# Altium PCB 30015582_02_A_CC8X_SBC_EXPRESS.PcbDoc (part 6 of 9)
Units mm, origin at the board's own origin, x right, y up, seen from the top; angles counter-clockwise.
Board outline 87 x 63 mm, 6 copper layers (Top Layer-L1, GND Plane-L2, Signal-L3, PWR/Signal-L4, GND Plane-L5, Bottom Layer-L6), stack 1.172 mm thick; 169 components, 171 nets, 693 pads, 391 vias.
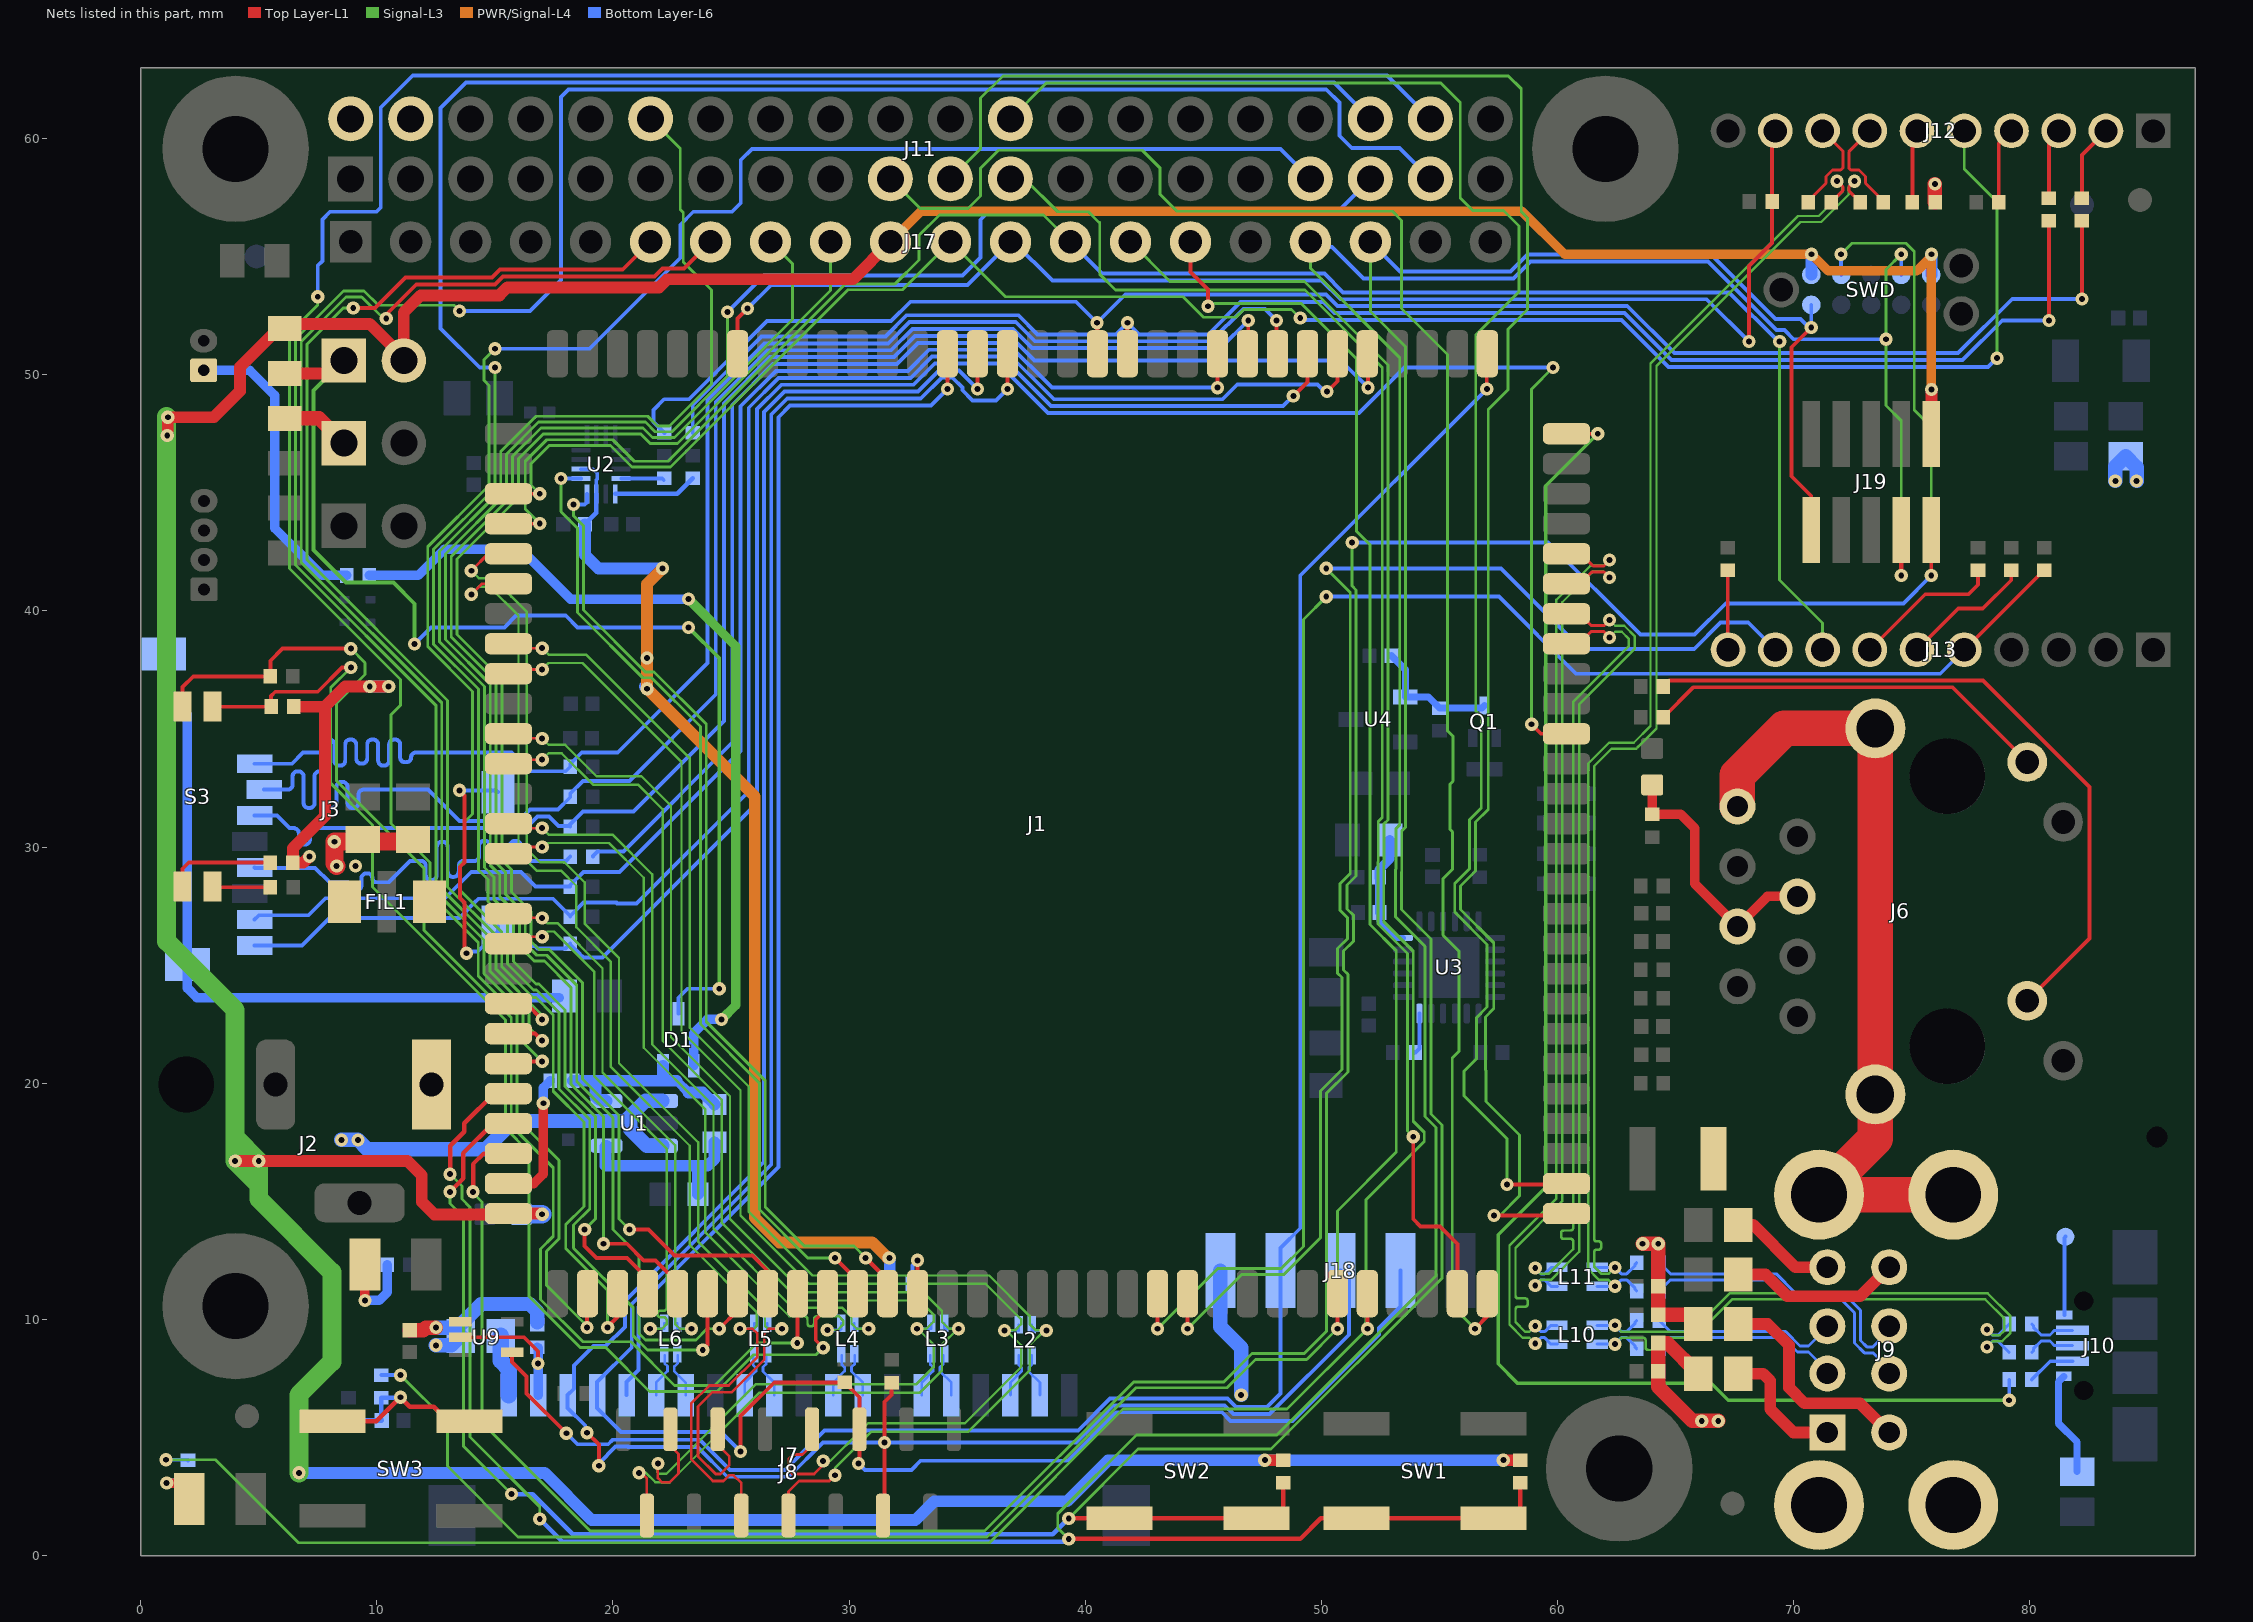
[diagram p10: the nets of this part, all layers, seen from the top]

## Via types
v1: diameter 0.56, hole 0.25, Top Layer-L1 to Bottom Layer-L6, 391 vias

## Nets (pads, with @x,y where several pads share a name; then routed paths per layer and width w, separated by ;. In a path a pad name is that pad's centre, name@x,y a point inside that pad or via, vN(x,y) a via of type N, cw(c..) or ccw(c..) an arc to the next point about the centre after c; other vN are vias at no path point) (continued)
MCA_IO1: J1.52 J17.6 | length 50.8
  Top Layer-L1 w0.165: v1(9,52.825) 9.925,52.825 11.21,54.11 14.877,54.11 15.217,54.45 20.414,54.45 J17.6@21.59,55.626 ; J1.52@15.573,23.368 16.332,23.368 v1(17,22.7)
  Signal-L3 w0.122: v1(9,52.825) 8.576,52.825 7.05,51.299 7.05,42.154 12.996,36.208 12.996,28.312 15.039,26.27 15.039,24.844 17,22.882 v1(17,22.7)
MCA_IO2: J1.53 J17.7 | length 55.3
  Top Layer-L1 w0.165: v1(10.4,52.375) 10.4,52.55 11.668,53.818 14.998,53.818 15.338,54.158 21.759,54.158 22.102,54.501 23.005,54.501 J17.7@24.13,55.626 ; J1.53@15.573,22.098 16.702,22.098 v1(17,21.8)
  Signal-L3 w0.122: v1(10.4,52.375) 10.277,52.375 9.359,53.293 8.692,53.293 6.801,51.402 6.801,42.051 12.747,36.105 12.747,28.209 14.79,26.166 14.79,24.741 16.438,23.092 16.438,22.362 v1(17,21.8)
MCA_IO3: J1.54 J11.37 | length 96.4
  Top Layer-L1 w0.165: J1.54@15.573,20.828 15.67,20.925 v1(17,20.925)
  Signal-L3 w0.122: v1(13.5,52.7) 13.262,52.938 10.065,52.938 9.462,53.542 8.589,53.542 6.552,51.505 6.552,41.948 12.498,36.002 12.498,28.106 14.541,26.063 14.541,24.637 16.189,22.989 16.189,21.736 v1(17,20.925)
  Bottom Layer-L6 w0.165: v1(13.5,52.7) 16.485,52.7 17.795,54.01 17.795,61.755 18.121,62.081 50.204,62.081 50.763,61.522 50.763,60.117 51.28,59.6 53.303,59.6 J11.37@54.61,58.293
MCA_IO4: J1.61 J11.38 | length 107.6
  Top Layer-L1 w0.165: v1(18.9,9.65) 18.9,11.065 J1.61@18.923,11.088
  Signal-L3 w0.121: 6.3,49.5 6.3,51.755 7.5,52.955 v1(7.5,53.3)
  Signal-L3 w0.122: 6.3,49.5 6.3,41.8 11,37.1 11,36 10.6,35.6 10.6,31 12.249,29.351 12.249,28.003 14.292,25.96 14.292,24.534 15.94,22.886 15.94,18.51 17.717,16.733 17.717,13.415 17.182,12.88 17.182,11.441 18.9,9.723 v1(18.9,9.65)
  Bottom Layer-L6 w0.165: v1(7.5,53.3) 7.5,54.621 7.692,54.813 7.692,56.577 8.014,56.9 9.985,56.9 10.165,57.08 10.165,61.311 11.519,62.665 52.778,62.665 J11.38@54.61,60.833
MCA_IO5: J1.62 J11.33 | length 89.2
  Top Layer-L1 w0.165: v1(19.775,9.65) 19.775,9.675 20.193,10.093 J1.62@20.193,11.088
  Signal-L3 w0.121: 14.751,48.5 14.751,49.549 14.533,49.767 14.533,50.632 v1(15,51.1)
  Signal-L3 w0.122: 14.751,48.5 14.751,45.311 12.155,42.716 12.155,38.484 14.055,36.584 14.055,31.4 13.71,31.055 13.71,29.45 13.5,29.24 13.5,28.187 15.287,26.4 15.287,24.947 16.612,23.622 16.74,23.622 17.468,22.894 17.468,19.657 18.768,18.357 18.768,14.782 18,14.014 18,12.993 19.775,11.218 v1(19.775,9.65)
  Bottom Layer-L6 w0.165: v1(15,51.1) 19,51.1 22.85,54.95 22.85,56.35 23.4,56.9 25.035,56.9 25.41,57.275 25.41,59.085 25.885,59.56 48.263,59.56 J11.33@49.53,58.293
MCA_IO6: J1.63 J11.12 | length 64.3
  Top Layer-L1 w0.165: v1(18.8,13.8) 18.8,13.1 19.3,12.6 20.6,12.6 21.463,11.737 J1.63@21.463,11.088
  Signal-L3 w0.121: 15.249,46.6 15.249,46.749 16.743,48.243 21.473,48.243 21.883,47.833 22.394,47.833 24.165,49.604 24.165,53.588 22.974,54.779 22.974,56.865 22.85,56.989 22.85,59.573 J11.12@21.59,60.833
  Signal-L3 w0.122: 15.249,46.6 15.249,45.105 12.653,42.509 12.653,38.691 14.553,36.791 14.553,29.128 14.953,28.728 14.953,27.791 15.785,26.959 15.785,25.153 16.738,24.2 16.866,24.2 17.966,23.1 17.966,19.863 19.266,18.563 19.266,14.266 v1(18.8,13.8)
MCA_IO7: J1.64 J11.35 | length 86.1
  Top Layer-L1 w0.165: v1(19.6,13.2) 20.6,13.2 21.3,12.5 21.8,12.5 22.733,11.567 J1.64@22.733,11.088
  Signal-L3 w0.121: 21.271,47.994 21.371,47.994 21.781,47.584 22.496,47.584 24.85,49.938 v1(24.85,52.65)
  Signal-L3 w0.122: v1(19.6,13.2) 19.6,18.581 18.215,19.966 18.215,24.047 17.094,25.168 16.666,25.168 16.034,25.8 16.034,27.062 15.202,27.894 15.202,28.831 14.802,29.231 14.802,36.894 12.902,38.794 12.902,42.406 15.498,45.002 15.498,46.646 16.846,47.994 21.271,47.994
  Bottom Layer-L6 w0.165: v1(24.85,52.65) 26.4,54.2 34.8,54.2 35.555,54.955 35.555,56.563 35.932,56.94 50.717,56.94 J11.35@52.07,58.293
MCA_IO8: J1.65 J11.36 | length 104.7
  Top Layer-L1 w0.165: v1(23.8,8.7) 24.003,8.903 J1.65@24.003,11.088
  Signal-L3 w0.122: v1(15,50.3) 15,45.208 12.404,42.612 12.404,38.588 14.304,36.688 14.304,29.025 14.704,28.625 14.704,27.688 15.536,26.856 15.536,25.05 16.635,23.951 16.763,23.951 17.717,22.997 17.717,19.76 19.017,18.46 19.017,14.679 18.332,13.994 18.332,13.013 20.858,10.487 20.858,9.303 21.461,8.7 v1(23.8,8.7)
  Bottom Layer-L6 w0.165: v1(15,50.3) 14.358,50.3 12.695,51.963 12.695,61.301 13.767,62.373 50.53,62.373 J11.36@52.07,60.833
MCA_IO9: J1.66 J17.8 | length 65.5
  Top Layer-L1 w0.165: v1(24.5,9.6) 25.273,10.373 J1.66@25.273,11.088
  Signal-L3 w0.122: v1(24.5,9.6) 23.987,9.6 23.519,9.132 21.381,9.132 21.107,9.406 21.107,12.693 20,13.8 20,18.533 18.464,20.069 18.464,24.15 17.197,25.417 16.769,25.417 16.283,25.903 16.283,27.165 15.451,27.997 15.451,28.934 15.051,29.334 15.051,36.997 13.151,38.897 13.151,42.303 15.747,44.899 15.747,46.543 16.949,47.745 21.268,47.745 21.678,47.336 22.599,47.336 27.6,52.337 27.6,54.696 J17.8@26.67,55.626
MCA_IO10: J1.67 J17.9 | length 63.1
  Top Layer-L1 w0.165: v1(20.7,13.8) 21.5,13.8 22.6,12.7 25.9,12.7 26.543,12.057 J1.67@26.543,11.088
  Signal-L3 w0.122: v1(20.7,13.8) 20.249,14.251 20.249,18.636 18.713,20.173 18.713,24.253 17.3,25.666 16.872,25.666 16.532,26.006 16.532,27.268 15.7,28.1 15.7,29.038 15.3,29.438 15.3,37.1 13.4,39 13.4,42.2 15.996,44.796 15.996,46.44 17.052,47.496 21.165,47.496 21.575,47.087 22.731,47.087 29.21,53.566 J17.9@29.21,55.626
MCA_VIN_DET: J1.58 R9.1 | length 5.7
  Top Layer-L1 w0.4: J1.58@15.573,15.748 16.648,15.748 17.05,16.15 v1(17.05,19.15)
  Bottom Layer-L6 w0.4: v1(17.05,19.15) 17.05,19.805 R9.1@17.345,20.1
MIPI_DSI0_CLK_N: J1.37 J8.11 L5.1 | length 52.8
  Top Layer-L1 w0.114: v1(14,41.7) 14.718,42.418 J1.37@15.573,42.418 ; J8.11@24.433,5.344 24.433,4.692 24.925,4.2 24.925,3.825 24.55,3.45 24.35,3.45 23.6,4.2 23.6,6.308 24.2,6.908 25.021,6.908 26.406,8.293 26.406,9.4 26.606,9.6 v1(27.15,9.6)
  Signal-L3 w0.102: v1(14,41.7) 14.322,41.378 14.925,41.378 15.7,40.603 16.356,39.947 16.356,29.907 16.907,29.356 17.947,29.356 18.797,28.506 18.797,26.755 20.256,25.297 20.256,20.847 23.606,17.497 23.606,13.294 26.438,10.462 26.438,9.719 26.557,9.6 v1(27.15,9.6)
  Bottom Layer-L6 w0.114: L5.1@26.534,9.837 26.534,9.6 v1(27.15,9.6)
MIPI_DSI0_CLK_P: J1.38 J8.10 L5.4 | length 52.8
  Top Layer-L1 w0.114: v1(14,40.7) 14.448,41.148 J1.38@15.573,41.148 ; v1(25.375,9.6) 25.914,9.6 26.114,9.4 26.114,8.414 24.9,7.2 24.079,7.2 23.308,6.429 23.308,4.079 24.229,3.158 24.671,3.158 24.907,3.393 25.107,3.393 25.433,3.067 J8.10@25.433,1.694
  Signal-L3 w0.102: v1(14,40.7) 14.322,41.022 14.778,41.022 16,39.8 16,29.76 16.76,29 17.8,29 18.442,28.358 18.442,26.608 19.9,25.15 19.9,20.7 23.25,17.35 23.25,13.147 26.082,10.315 26.082,9.719 25.963,9.6 v1(25.375,9.6)
  Bottom Layer-L6 w0.114: v1(25.375,9.6) 25.984,9.6 L5.4@25.984,9.837
MIPI_DSI0_DATA0_N: J1.40 J8.8 L2.1 | length 61.1
  Top Layer-L1 w0.114: J1.40@15.573,38.608 15.761,38.42 v1(17,38.42) ; J8.8@27.433,1.694 27.433,2.708 27.883,3.158 29.158,3.158 v1(29.4,3.4)
  Signal-L3 w0.102: v1(17,38.42) 17.272,38.148 18.855,38.148 23.256,33.747 23.256,22.347 25.756,19.847 25.756,14.544 28.444,11.856 35.931,11.856 37.639,10.147 37.639,9.8 37.907,9.532 v1@38.271,9.532 ; v1(29.4,3.4) 29.4,3.7 30.947,5.247 35.047,5.247 37.639,7.839 37.639,8.9 v1@38.271,9.532 ; v1(38.35,9.525) 38.278,9.525 v1@38.271,9.532
  Bottom Layer-L6 w0.114: L2.1@37.736,9.769 37.736,9.532 37.743,9.525 v1(38.35,9.525)
MIPI_DSI0_DATA0_P: J1.41 J8.7 L2.4 | length 61.1
  Top Layer-L1 w0.114: J1.41@15.573,37.338 15.755,37.52 v1(17,37.52) ; J8.7@28.433,5.344 28.433,4.683 28.025,4.275 27.625,4.275 27.45,4.1 27.45,3.593 27.593,3.45 28.517,3.45 28.9,3.833 v1(28.9,4)
  Signal-L3 w0.102: v1(17,37.52) 17.272,37.792 18.708,37.792 22.9,33.6 22.9,22.2 25.4,19.7 25.4,14.397 28.297,11.5 35.784,11.5 37.284,10 37.284,9.8 37.016,9.532 v1@36.652,9.532 ; v1(28.9,4) 29.197,4 30.497,5.3 30.8,5.603 34.9,5.603 37.284,7.986 37.284,8.9 v1@36.652,9.532 ; v1(36.575,9.525) 36.645,9.525 v1@36.652,9.532
  Bottom Layer-L6 w0.114: v1(36.575,9.525) 37.179,9.525 37.186,9.532 L2.4@37.186,9.769
MIPI_DSI0_DATA1_N: J1.43 J8.14 L3.1 | length 58.4
  Top Layer-L1 w0.114: J1.43@15.573,34.798 15.771,34.6 v1(17,34.6) ; v1(21.1,3.5) 21.2,3.5 21.433,3.267 J8.14@21.433,1.694
  Signal-L3 w0.102: v1(17,34.6) 17.272,34.328 17.972,34.328 19.3,33 21.2,33 22.456,31.744 22.456,21.947 24.956,19.447 24.956,14.244 28.044,11.156 33.122,11.156 33.931,10.347 33.931,9.9 34.231,9.6 v1@34.603,9.6 ; v1(21.1,3.5) 21.397,3.5 21.797,3.1 22.4,3.1 26.2,6.9 33,6.9 33.931,7.831 33.931,8.928 v1@34.603,9.6 ; v1(34.626,9.6) v1@34.603,9.6
  Bottom Layer-L6 w0.114: L3.1@34.027,9.837 34.027,9.6 v1(34.626,9.6)
MIPI_DSI0_DATA1_P: J1.44 J8.13 L3.4 | length 58.4
  Top Layer-L1 w0.114: J1.44@15.573,33.528 15.745,33.7 v1(17,33.7) ; v1(21.9,3.9) 21.9,3.275 22.075,3.1 22.4,3.1 22.775,3.475 22.775,4.3 22.433,4.642 J8.13@22.433,5.344
  Signal-L3 w0.102: v1(17,33.7) 17.272,33.972 17.825,33.972 19.153,32.644 21.053,32.644 22.1,31.597 22.1,21.8 24.6,19.3 24.6,14.097 27.897,10.8 32.975,10.8 33.575,10.2 33.575,9.9 33.275,9.6 v1@32.903,9.6 ; v1(21.9,3.9) 21.9,3.5 21.944,3.456 22.253,3.456 26.053,7.256 32.853,7.256 33.575,7.978 33.575,8.928 v1@32.903,9.6 ; v1(32.875,9.6) v1@32.903,9.6
  Bottom Layer-L6 w0.114: v1(32.875,9.6) 33.477,9.6 L3.4@33.477,9.837
MIPI_DSI0_DATA2_N: J1.46 L4.1 | length 32.4
  Top Layer-L1 w0.114: J1.46@15.573,30.988 15.761,30.8 v1(17,30.8)
  Signal-L3 w0.102: v1(17,30.8) 17.272,30.528 19.975,30.528 21.656,28.847 21.656,21.647 24.256,19.047 24.256,13.844 27.613,10.487 29.713,10.487 30.1,10.1 30.1,9.821 30.321,9.6 v1(30.825,9.6)
  Bottom Layer-L6 w0.114: L4.1@30.217,9.837 30.217,9.6 v1(30.825,9.6)
MIPI_DSI0_DATA2_P: J1.47 L4.4 | length 32.4
  Top Layer-L1 w0.114: J1.47@15.573,29.718 15.855,30 v1(17,30)
  Signal-L3 w0.102: v1(17,30) 17.1,30 17.272,30.172 19.828,30.172 21.3,28.7 21.3,21.5 23.9,18.9 23.9,13.697 27.466,10.132 27.975,10.132 28.111,10.132 cw(c28.111,10.007) 28.235,10.007 28.235,9.825 ccw(c28.36,9.825) 28.36,9.7 28.387,9.7 ccw(c28.387,9.825) 28.512,9.825 28.512,10.007 cw(c28.636,10.007) 28.636,10.132 28.65,10.132 29.566,10.132 29.744,9.953 29.744,9.779 29.515,9.55 v1(29.075,9.55)
  Bottom Layer-L6 w0.114: v1(29.075,9.55) 29.617,9.55 29.667,9.6 L4.4@29.667,9.837
MIPI_DSI0_DATA3_N: J1.49 L6.1 | length 22.9
  Top Layer-L1 w0.114: J1.49@15.573,27.178 15.751,27 v1(17,27)
  Signal-L3 w0.102: v1(17,27) 17.222,26.778 17.647,26.778 19.556,24.869 19.556,20.447 22.628,17.375 22.628,10.607 22.635,10.601 22.635,10.489 22.637,10.489 22.637,10.449 22.632,10.444 22.632,10.404 22.629,10.401 22.629,10.362 22.628,10.092 22.629,10.052 22.632,10.049 22.632,10.009 22.637,10.004 22.637,9.964 22.635,9.964 22.635,9.853 22.628,9.846 22.628,9.8 22.828,9.6 v1(23.325,9.6)
  Bottom Layer-L6 w0.114: L6.1@22.724,9.837 22.724,9.6 v1(23.325,9.6)
MIPI_DSI0_DATA3_P: J1.50 L6.4 | length 22.9
  Top Layer-L1 w0.114: J1.50@15.573,25.908 15.865,26.2 v1(17,26.2)
  Signal-L3 w0.102: v1(17,26.2) 17.222,26.422 17.5,26.422 19.2,24.722 19.2,20.3 22.272,17.228 22.272,10.55 22.272,10.489 cw(c22.148,10.489) 22.148,10.365 22.008,10.365 ccw(c22.008,10.24) 21.883,10.24 21.883,10.213 ccw(c22.008,10.213) 22.008,10.088 22.148,10.088 cw(c22.148,9.964) 22.272,9.964 22.272,9.95 22.272,9.8 22.072,9.6 v1(21.575,9.6)
  Bottom Layer-L6 w0.114: v1(21.575,9.6) 22.174,9.6 L6.4@22.174,9.837
MIPI_DSI0_I2C0_SCL: J1.17 J7.17 J8.5 J18.4 R74.1 | length 102.9
  Top Layer-L1 w0.165: v1(25.4,4.4) 25.4,5.9 26.827,7.327 R74.1@29.807,7.327 30.433,6.701 J8.5@30.433,5.344 30.433,3.933 v1(30.4,3.9) ; v1(36.703,49.4) J1.17@36.703,50.888
  Bottom Layer-L6 w0.165: v1(25.4,4.4) 24.574,5.226 20.347,5.226 19.328,6.244 J7.17@19.328,6.794 19.328,7.344 20.793,8.809 20.793,10.655 26.7,16.562 26.7,48.313 27.379,48.992 33.031,48.992 33.929,49.89 34.366,49.89 34.798,49.457 34.798,49.343 35.23,48.91 36.213,48.91 v1(36.703,49.4) ; v1(30.4,3.9) 30.672,3.628 32.636,3.628 33.019,4.011 39.238,4.011 41.291,6.065 45.782,6.065 46.145,5.701 48.769,5.701 52.433,9.365 52.433,9.633 53.34,10.54 J18.4@53.34,12.065
MIPI_DSI0_I2C0_SDA: J1.18 J7.18 J8.4 J18.3 R75.1 | length 104.6
  Top Layer-L1 w0.165: v1(18.9,5.2) 19.4,4.7 v1(19.4,3.8) ; J8.4@31.433,1.694 31.5,1.761 v1(31.5,4.789) 31.5,6.5 31.8,6.8 R75.1@31.8,7.32 ; v1(35.433,49.4) J1.18@35.433,50.888
  Bottom Layer-L6 w0.165: v1(18.9,5.2) 18.824,5.276 18.824,5.498 18.078,6.244 J7.18@18.078,6.794 18.346,7.062 18.346,8.038 19.181,8.873 19.69,8.873 20.501,9.684 20.501,10.776 26.4,16.675 26.4,48.426 27.258,49.284 32.91,49.284 33.808,50.182 34.651,50.182 v1(35.433,49.4) ; v1(19.4,3.8) 19.4,3.9 20.107,4.607 20.636,4.607 20.644,4.6 23.573,4.6 24.836,3.336 27.443,3.336 28.896,4.789 v1(31.5,4.789) 39.602,4.789 41.17,6.357 45.903,6.357 46.266,5.994 47.807,5.994 51.163,9.349 51.163,11.702 J18.3@50.8,12.065
MIPI_DSI0_IRQ_N: J1.1 J18.2 U9.4 | length 84.7
  Top Layer-L1 w0.165: U9.4@15.725,8.6 15.725,8.185 16.335,7.575 16.335,6.865 v1(18.025,5.175) ; v1(57,49.4) 57,50.865 J1.1@57.023,50.888
  Bottom Layer-L6 w0.165: v1(18.025,5.175) 18.49,4.71 19.797,4.71 19.986,4.9 23.686,4.9 24.957,3.628 27.285,3.628 28.957,5.3 39.7,5.3 41.049,6.649 46.024,6.649 46.387,6.286 47.686,6.286 48.26,6.86 J18.2@48.26,12.065 48.26,13.018 49.1,13.858 49.1,41.5 v1(57,49.4)
MIPI_DSI0_PWM0_OUT: J1.19 J7.16 | length 53.2
  Top Layer-L1 w0.165: v1(34.163,49.4) J1.19@34.163,50.888
  Bottom Layer-L6 w0.165: J7.16@20.578,6.794 20.578,7.344 21.085,7.852 21.085,10.534 27,16.449 27,48.2 27.5,48.7 33.463,48.7 v1(34.163,49.4)
NetC20_2: C20.2 J6.4 J6.5 R39.2 | length 11.3
  Top Layer-L1 w0.4: C20.2@64,32.63 R39.2@64,31.38 65.22,31.38 65.8,30.8 65.8,28.451 J6.4@67.613,26.638 68.883,27.908 J6.5@70.153,27.908
NetC28_2: C28.2 R60.1 R61.2 SW3.3 SW3.4 | length 9.8
  Top Layer-L1 w0.2: SW3.4@8.119,5.683 9.983,5.683 v1(11,6.7) 11.4,6.3 12.4,6.3 13.017,5.683 SW3.3@13.919,5.683
  Bottom Layer-L6 w0.2: R60.1@8.8,5.72 8.805,5.715 C28.2@10.208,5.715 10.189,5.734 R61.2@10.189,6.675 10.975,6.675 v1(11,6.7)
NetC32_1: C32.1 Q1.D R72.1 U4.G | length 5.6
  Bottom Layer-L6 w0.3: C32.1@52.96,38.1 53.55,37.51 U4.G@53.55,36.35 54.53,36.35 R72.1@55,35.88 55.002,35.882 56.531,35.882 56.533,35.88 56.79,35.88 Q1.D@56.9,35.99
NetD1_2: D1.2 R6.2 R9.2 U1.5 | length 8.2
  Bottom Layer-L6 w0.4: 22.7,20.1 23.2,19.6
  Bottom Layer-L6 w0.5: R9.2@18.305,20.1 19.264,20.1 ; U1.5@19.72,19.25 19.67,19.3 19.4,19.3 19.264,19.436 19.264,20.1 ; D1.2@22.12,20.74 22.12,20.1 ; 22.7,20.1 22.12,20.1 ; 23.2,19.6 23.8,19.6 R6.2@24.3,19.1 ; 19.264,20.1 22.12,20.1
NetD1_3: D1.3 J16.1 R8.1 | length 48.9
  Top Layer-L1 w0.5: R8.1@6.1,50.05 8.05,50.05 J16.1@8.6,50.6
  Signal-L3 w0.165: J16.1@8.6,50.6 7.325,49.325 7.325,42.575 8.7,41.2 10.7,41.2 11.6,40.3 v1(11.6,38.6) ; v1(23.2,39.3) 24.5,38 v1(24.5,24)
  Bottom Layer-L6 w0.165: v1(11.6,38.6) 12.3,39.3 15.4,39.3 15.9,39.8 18,39.8 18.5,39.3 v1(23.2,39.3) ; D1.3@22.77,22.94 22.77,23.619 23.151,24 v1(24.5,24)
NetD4_A: D4.A R59.1 | length 2.5
  Top Layer-L1 w0.4: v1(1.1,3.065) 2.056,3.065 D4.A@2.056,2.402
  Bottom Layer-L6 w0.4: v1(1.1,3.065) R59.1@2.003,3.065
NetD5_A: D5.A R68.2 | length 3.8
  Top Layer-L1 w0.4: D5.A@9.495,12.319 9.495,10.805 v1(9.5,10.8)
  Bottom Layer-L6 w0.4: v1(9.5,10.8) 10.1,10.8 10.442,11.142 R68.2@10.442,12.319
NetFIL1_1: FIL1.1 J2.1
NetJ1_72: J1.72 R3.1 | length 2.5
  Top Layer-L1 w0.165: J1.72@32.893,11.088 v1(32.893,12.5)
  Bottom Layer-L6 w0.165: R3.1@32.68,11.5 32.68,12.287 v1(32.893,12.5)
NetJ3_5: J3.5 R19.2 | length 21.6
  Bottom Layer-L6 w0.165: J3.5@4.826,29.128 4.844,29.11 7.39,29.11 7.99,28.51 8.3,28.51 8.703,28.51 cw(c8.703,28.331) 8.883,28.331 ; 8.883,28.339 8.883,28.363 ; 8.883,28.371 ccw(c9.092,28.371) 9.092,28.162 9.139,28.162 ccw(c9.139,28.371) 9.348,28.371 9.348,28.51 9.348,28.672 cw(c9.557,28.672) 9.557,28.881 9.604,28.881 cw(c9.604,28.672) 9.813,28.672 ccw(c9.974,28.672) 9.974,28.51 10.278,28.51 10.51,28.51 11.41,29.41 11.607,29.41 11.863,29.41 cw(c11.863,29.201) 12.072,29.201 12.072,28.81 ccw(c12.282,28.81) 12.282,28.601 12.328,28.601 ccw(c12.328,28.81) 12.537,28.81 12.537,29.41 12.537,30.011 cw(c12.747,30.011) 12.747,30.22 12.793,30.22 cw(c12.793,30.011) 13.002,30.011 13.002,29.41 13.002,28.948 ccw(c13.212,28.948) 13.212,28.739 13.258,28.739 ccw(c13.258,28.948) 13.467,28.948 13.467,29.201 cw(c13.677,29.201) 13.677,29.41 13.7,29.41 14.1,29.41 14.123,29.41 ccw(c14.123,29.62) 14.333,29.62 14.333,30.051 cw(c14.542,30.051) 14.542,30.26 14.588,30.26 cw(c14.588,30.051) 14.798,30.051 14.798,29.613 ccw(c15,29.613) 15,29.41 15.4,29.41 15.423,29.41 ccw(c15.423,29.62) 15.633,29.62 15.633,30.051 cw(c15.842,30.051) 15.842,30.26 15.888,30.26 cw(c15.888,30.051) 16.098,30.051 16.098,29.62 ccw(c16.307,29.62) 16.307,29.41 16.504,29.41 18.008,29.41 R19.2@18.189,29.591
NetJ3_11: J3.11 J3.12 R20.2 | length 30.5
  Bottom Layer-L6 w0.4: J3.12@0.976,38.178 0.976,36.624 1.976,35.624 J3.11@1.976,25.028 1.976,24.024 2.378,23.622 R20.2@17.719,23.622
NetJ4_1: J4.1 R69.1 | length 12.9
  Bottom Layer-L6 w0.4: J4.1@2.667,50.185 4.615,50.185 5.675,49.125 5.675,43.5 7.675,41.5 R69.1@8.72,41.5
NetJ6_10: J6.10 R40.1 | length 30.2
  Top Layer-L1 w0.165: R40.1@64.48,36.8 64.74,37.06 78.006,37.06 82.523,32.542 82.523,26.129 J6.10@79.883,23.488
NetJ6_12: J6.12 R41.2 | length 17.2
  Top Layer-L1 w0.15: R41.2@64.48,35.5 65.755,36.775 76.706,36.775 J6.12@79.883,33.598
NetJ7_2: J7.2 L2.2 | length 1.9
  Bottom Layer-L6 w0.114: L2.2@37.736,8.469 37.736,8.086 37.599,7.949 37.599,7.801 38.078,7.322 J7.2@38.078,6.794
NetJ7_3: J7.3 L2.3 | length 1.9
  Bottom Layer-L6 w0.114: J7.3@36.828,6.794 36.828,7.328 37.307,7.807 37.307,7.943 37.186,8.064 L2.3@37.186,8.469
NetJ7_5: J7.5 L3.2 | length 1.9
  Bottom Layer-L6 w0.114: L3.2@33.986,8.469 33.986,8.111 33.849,7.974 33.849,7.801 34.328,7.322 J7.5@34.328,6.794
NetJ7_6: J7.6 L3.3 | length 1.9
  Bottom Layer-L6 w0.114: J7.6@33.078,6.794 33.078,7.328 33.557,7.807 33.557,7.968 33.436,8.089 L3.3@33.436,8.469
NetJ7_8: J7.8 L4.2 | length 1.9
  Bottom Layer-L6 w0.114: L4.2@30.236,8.469 30.236,8.111 30.099,7.974 30.099,7.801 30.578,7.322 J7.8@30.578,6.794
NetJ7_9: J7.9 L4.3 | length 1.9
  Bottom Layer-L6 w0.114: J7.9@29.328,6.794 29.328,7.328 29.807,7.807 29.807,7.968 29.686,8.089 L4.3@29.686,8.469
NetJ7_11: J7.11 L5.2 | length 1.9
  Bottom Layer-L6 w0.114: L5.2@26.486,8.469 26.486,8.111 26.349,7.974 26.349,7.801 26.828,7.322 J7.11@26.828,6.794
NetJ7_12: J7.12 L5.3 | length 1.9
  Bottom Layer-L6 w0.114: J7.12@25.578,6.794 25.578,7.328 26.057,7.807 26.057,7.943 25.936,8.064 L5.3@25.936,8.469
NetJ7_14: J7.14 L6.2 | length 1.9
  Bottom Layer-L6 w0.114: L6.2@22.736,8.469 22.736,8.136 22.599,7.999 22.599,7.801 23.078,7.322 J7.14@23.078,6.794
NetJ7_15: J7.15 L6.3 | length 1.9
  Bottom Layer-L6 w0.114: J7.15@21.828,6.794 21.828,7.328 22.307,7.807 22.307,8.018 22.186,8.139 L6.3@22.186,8.469
NetJ7_19: J7.19 R43.2 U9.2 | length 6.1
  Top Layer-L1 w0.15: U9.2@13.525,9.25 16.225,9.25 16.825,8.65 v1(16.825,8.125)
  Bottom Layer-L6 w0.4: R43.2@16.8,8.82 16.828,8.792 J7.19@16.828,6.794
NetJ7_20: J7.20 L7.2 | length 2.6
  Bottom Layer-L6 w0.7: L7.2@15.25,9.3 15.25,8.25 15.578,7.922 J7.20@15.578,6.794
NetJ9_A1: J9.A1 L9.1 | length 5.5
  Top Layer-L1 w0.5: L9.1@67.65,7.7 68.7,7.7 69,7.4 69,6.2 69.993,5.207 J9.A1@71.421,5.207
NetJ9_A2: J9.A2 R44.2 | length 8
  Bottom Layer-L6 w0.127: R44.2@64.305,8.75 64.778,9.223 69.552,9.223 70.154,8.621 70.625,8.621 71.421,7.825 J9.A2@71.421,7.707
NetJ9_A3: J9.A3 R45.2 | length 7.9
  Bottom Layer-L6 w0.127: R45.2@64.305,9.95 64.778,9.477 69.657,9.477 70.259,8.875 70.625,8.875 71.421,9.671 J9.A3@71.421,9.707
NetJ9_A4: J9.A4 L13.2 | length 4.5
  Top Layer-L1 w0.5: L13.2@67.65,14 68.275,14 70.068,12.207 J9.A4@71.421,12.207
NetJ9_B1: J9.B1 L8.1 | length 9.3
  Top Layer-L1 w0.5: L8.1@67.65,9.8 68.9,9.8 69.8,8.9 69.8,7.1 70.45,6.45 72.798,6.45 J9.B1@74.041,5.207
NetJ9_B2: J9.B2 R46.2 | length 12.4
  Bottom Layer-L6 w0.127: R46.2@64.305,11.2 64.778,11.673 69.152,11.673 69.95,10.875 71.975,10.875 72.571,10.279 72.571,8.995 72.986,8.58 73.35,8.58 74.041,7.889 J9.B2@74.041,7.707
NetJ9_B3: J9.B3 R47.2 | length 12.4
  Bottom Layer-L6 w0.127: R47.2@64.305,12.4 64.778,11.927 69.257,11.927 70.055,11.129 72.08,11.129 72.825,10.384 72.825,9.1 73.091,8.834 73.35,8.834 74.041,9.525 J9.B3@74.041,9.707
NetJ9_B4: J9.B4 L12.2 | length 7.3
  Top Layer-L1 w0.5: L12.2@67.65,11.9 68.8,11.9 69.725,10.975 72.809,10.975 J9.B4@74.041,12.207
NetJ10_1: J10.1 TP3.1 | length 3.3
  Bottom Layer-L6 w0.165: J10.1@81.455,10.183 81.455,13.455 TP3.1@81.5,13.5
NetJ10_2: J10.2 R48.1 | length 2
  Bottom Layer-L6 w0.127: R48.1@80.08,9.8 80.143,9.737 80.143,9.667 80.475,9.335 80.844,9.335 81.042,9.533 J10.2@81.805,9.533
NetJ10_3: J10.3 R49.1 | length 2.1
  Bottom Layer-L6 w0.127: R49.1@80.08,8.6 80.143,8.664 80.143,8.749 80.475,9.081 80.844,9.081 81.042,8.883 J10.3@81.805,8.883
NetJ10_4: J10.4 R76.1 | length 2
  Bottom Layer-L6 w0.15: R76.1@80.08,7.45 80.863,8.233 J10.4@81.805,8.233
NetJ10_5: J10.5 L14.2 | length 4.5
  Bottom Layer-L6 w0.3: J10.5@81.43,7.583 81.2,7.353 81.2,5.6 82,4.8 L14.2@82,3.55
NetJ12_2: J12.2 R62.2 | length 3.3
  Top Layer-L1 w0.165: R62.2@82.2,57.48 82.2,59.2 82.2,59.308 J12.2@83.217,60.325
NetJ12_3: J12.3 R63.2 | length 3
  Top Layer-L1 w0.165: R63.2@80.8,57.48 80.8,59.2 80.8,59.908 J12.3@81.217,60.325
NetJ12_4: J12.4 R50.2 | length 3.2
  Top Layer-L1 w0.165: R50.2@78.68,57.3 78.68,59.2 78.68,59.788 J12.4@79.217,60.325
NetJ12_6: J12.6 R51.2 | length 3.1
  Top Layer-L1 w0.165: R51.2@75.02,57.3 75.02,59.2 75.02,60.128 J12.6@75.217,60.325
NetJ12_7: J12.7 R52.2 | length 4.2
  Top Layer-L1 w0.127: J12.7@73.217,60.325 72.327,59.435 72.327,58.753 72.415,58.665 72.763,58.665 73.039,58.389 73.039,58.111 73.78,57.37 R52.2@73.78,57.3
NetJ12_8: J12.8 R53.2 | length 4.2
  Top Layer-L1 w0.127: R53.2@70.62,57.3 70.62,57.37 71.361,58.111 71.361,58.389 71.637,58.665 71.985,58.665 72.073,58.753 72.073,59.469 J12.8@71.217,60.325
NetJ13_6: J13.6 R55.1 | length 5.6
  Top Layer-L1 w0.15: J13.6@75.217,38.354 76.963,40.1 78,40.1 79.2,41.3 R55.1@79.2,41.72
NetJ13_7: J13.7 R56.1 | length 6.3
  Top Layer-L1 w0.15: J13.7@73.217,38.354 75.563,40.7 77.4,40.7 77.8,41.1 R56.1@77.8,41.72
NetJ13_10: J13.10 R58.1 | length 3.4
  Top Layer-L1 w0.15: R58.1@67.2,41.72 67.2,38.371 J13.10@67.217,38.354
NetR6_1: R6.1 R7.2 U1.4 | length 7.6
  Bottom Layer-L6 w0.5: U1.4@19.72,17.35 19.68,17.31 19.68,16.5 23.5,16.5 ; R7.2@23.6,15.3 23.6,16.4 23.5,16.5 ; R6.1@24.3,17.5 24.3,16.8 24,16.5 23.5,16.5
NetR12_2: R12.2 S3.4 | length 2.5
  Top Layer-L1 w0.15: S3.4@3.048,28.321 3.069,28.3 R12.2@5.495,28.3
NetR13_1: R13.1 S3.3 | length 4.6
  Top Layer-L1 w0.165: S3.3@1.778,28.321 1.778,29.078 2.037,29.337 R13.1@5.489,29.337
NetR38_2: R38.2 U3.24 | length 1.7
  Bottom Layer-L6 w0.165: R38.2@53.98,21.3 54.15,21.47 U3.24@54.15,22.95
NetR64_2: R64.2 U2.5 | length 3.6
  Bottom Layer-L6 w0.2: U2.5@20.096,44.955 22.715,44.955 R64.2@23.375,45.615
NetR65_2: R65.2 U2.4 | length 1.8
  Bottom Layer-L6 w0.15: U2.4@20.346,45.605 22.085,45.605 R65.2@22.15,45.54
SCU_BOOT_MODE0: J1.68 R11.2 S3.2 | length 56.6
  Top Layer-L1 w0.165: S3.2@1.778,35.941 1.778,36.778 2.225,37.225 R11.2@5.489,37.225 5.489,37.889 6,38.4 v1(8.9,38.4) ; v1(27.8,9) 27.813,9.013 J1.68@27.813,11.088
  Signal-L3 w0.122: v1(8.9,38.4) 9.5,37.8 9.5,37.3 8.3,36.1 8.3,32.8 12,29.1 12,26.474 15.691,22.783 15.691,18.195 17.468,16.418 17.468,13.518 16.933,12.983 16.933,10.842 18.726,9.049 20.76,9.049 22.609,7.2 24.298,7.2 26.098,9 v1(27.8,9)
SCU_BOOT_MODE1: J1.69 R10.1 S3.1 | length 54.8
  Top Layer-L1 w0.165: S3.1@3.048,35.941 5.511,35.941 R10.1@5.52,35.95 5.52,36.395 5.7,36.575 7.5,36.575 8.525,37.6 v1(8.9,37.6) ; v1(28.9,8.8) 28.585,9.115 28.585,9.985 29.083,10.483 J1.69@29.083,11.088
  Signal-L3 w0.122: v1(8.9,37.6) 8.051,36.751 8.051,32.697 9.817,30.931 9.817,28.305 15.442,22.68 15.442,18.092 16.442,17.092 16.442,10.981 18.623,8.8 19.7,8.8 21.549,6.951 24.401,6.951 25.95,8.5 28.6,8.5 v1(28.9,8.8)
SD_CARD_DETECT: J1.108 J3.9 J3.10 R70.1 | length 95.1
  Top Layer-L1 w0.165: v1(13.5,32.4) 13.71,32.19 13.71,29.35 13.525,29.165 13.525,27.835 13.71,27.65 13.71,25.59 v1(13.8,25.5) ; v1(58.9,35.2) 59.302,34.798 J1.108@60.373,34.798
  Signal-L3 w0.121: v1(58.9,35.2) 58.9,49.4 v1(59.8,50.3)
  Signal-L3 w0.122: v1(13.5,32.4) v1@13.6,32.4
  Bottom Layer-L6 w0.165: v1(13.5,32.4) 15.054,32.4 J3.9@15.126,32.328 ; v1(13.8,25.5) 13.876,25.576 14.274,25.576 J3.10@15.126,26.428 ; J3.10@15.126,26.628 J3.10@15.126,26.428 ; v1(59.8,50.3) 53.517,50.3 51.594,48.376 38.424,48.376 36.326,50.474 33.626,50.474 32.729,49.576 27.137,49.576 26.1,48.539 26.1,31.864 19.551,25.315 18.747,25.315 18.581,25.481 18.581,25.491 18.189,25.883 R70.1@18.189,25.908 17.992,25.71 16.797,25.71 16.697,25.811 15.743,25.811 J3.10@15.126,26.428
SHLD: J6.8 J6.SHLD1 J6.SHLD2 J9.SH1 J9.SH2 J9.SH3 J9.SH4 R42.2 | length 34.4
  Top Layer-L1 w1.5: J6.8@67.613,31.718 67.613,33.038 69.598,35.023 J6.SHLD2@73.453,35.023 J6.SHLD1@73.453,19.523 73.453,17.659 J9.SH4@71.071,15.277 J9.SH3@76.751,15.277
SPI3_CS0: J1.93 J11.24 | length 73.2
  Top Layer-L1 w0.165: v1(57.855,15.71) 60.335,15.71 J1.93@60.373,15.748
  Signal-L3 w0.121: J11.24@36.83,60.833 38.342,62.345 55.053,62.345 55.875,61.524 55.875,57.48 56.405,56.95 57.705,56.95 58.361,56.295 58.361,53.511 56.533,51.683 56.533,35.754 56.767,35.519 56.767,31.653 56.272,31.157 56.272,29.083 55.642,28.453 55.642,27.252 57.015,25.878 57.015,23.229 56.56,22.774 56.56,21.035 56.032,20.507 56.032,19.471 57.855,17.648 v1(57.855,15.71)
SPI3_SCK: J1.90 J11.23 | length 61.5
  Top Layer-L1 w0.165: v1(53.885,17.73) 53.885,14.245 54.2,13.93 55.02,13.93 55.753,13.197 J1.90@55.753,11.088
  Signal-L3 w0.121: J11.23@36.83,58.293 37.437,58.293 38.83,56.9 40.135,56.9 40.585,56.45 40.61,56.45 40.61,54.255 41.28,53.585 49.295,53.585 52.57,50.31 52.57,31.25 52.405,31.085 52.405,29.372 52.389,29.355 52.389,26.736 53.639,25.486 53.639,17.976 v1(53.885,17.73)
SPI3_SDI: J1.92 J11.21 | length 81.5
  Top Layer-L1 w0.165: v1(57.3,14.4) 60.295,14.4 J1.92@60.373,14.478
  Signal-L3 w0.121: J11.21@34.29,58.293 35.565,59.568 35.565,61.71 36.51,62.655 57.91,62.655 58.46,62.105 58.46,56.905 58.73,56.635 58.73,52.755 57.9,51.925 57.9,49.365 57.06,48.525 57.06,31.595 56.52,31.055 56.52,29.815
  Signal-L3 w0.122: 56.52,29.815 56.52,28.98 55.89,28.35 55.89,27.355 57.295,25.95 57.295,23.157 56.945,22.807 56.945,20.565 56.968,20.542 56.968,19.222 58.385,17.805 58.385,15.23 57.555,14.4 v1(57.3,14.4)
SPI3_SDO: J1.91 J11.19 | length 76.4
  Top Layer-L1 w0.165: v1(56.5,9.6) 57.1,10.2 57.1,11.011 J1.91@57.023,11.088
  Signal-L3 w0.122: J11.19@31.75,58.293 33.008,57.035 35.035,57.035 35.568,57.568 35.568,58.744 36.328,59.504 42.412,59.504 43.155,58.761 43.155,57.65 43.885,56.92 53.005,56.92 53.39,56.535 53.39,52.805 55.336,50.859 55.336,34.926 55.568,34.694 55.568,32.788 55.436,32.656 55.436,30.751 55.543,30.644 55.543,29.056 55.145,28.659 55.145,26.267 55.816,25.597 55.816,21.343 55.536,21.064 55.536,10.564 v1(56.5,9.6)
SWD_CLK/PWR_IO: J1.55 J17.17 J19.4 R4.2 SW1.3 SW1.4 SWD.4 | length 176
  Top Layer-L1 w0.191: v1(13.102,16.148) 13.102,17.344 13.7,17.942 13.7,18.297 14.961,19.558 J1.55@15.573,19.558 ; v1(39.3,0.7) 49.1,0.7 49.972,1.572 SW1.3@51.479,1.572 SW1.4@57.279,1.572 58.42,1.572 R4.2@58.42,3.076 ; v1(74.549,41.5) J19.4@74.549,43.434
  Signal-L3 w0.122: v1(13.102,16.148) 13.6,15.65 13.6,15.1 13.95,14.75 13.95,5.012 16.9,2.062 v1(16.9,1.544) ; v1(39.3,0.7) 38.832,1.168 38.832,1.766 42.17,5.104 48.109,5.104 54.849,11.844 54.849,18.129 54.383,18.595 54.383,25.795 53.133,27.045 53.133,29.047 53.149,29.063 53.149,30.777 53.314,30.942 53.314,50.721 49.53,54.505 J17.17@49.53,55.626 ; v1(74.549,41.5) 74.549,48.049 73.9,48.698 v1(73.9,51.5) 73.9,54.45 v1(74.55,55.1)
  Bottom Layer-L6 w0.165: J17.17@49.53,55.626 49.75,55.406 50.449,55.406 51.782,54.073 58.129,54.073 58.846,54.79 66.372,54.79 69.272,51.89 69.603,51.89 69.992,51.5 v1(73.9,51.5) ; SWD.4@74.549,54.229 74.55,54.23 v1(74.55,55.1)
  Bottom Layer-L6 w0.191: v1(16.9,1.544) 17.862,0.583 39.182,0.583 v1(39.3,0.7)
SWD_DIO/MCA_IO21: J1.57 J19.2 SWD.2 | length 135.8
  Top Layer-L1 w0.165: v1(75.819,41.5) J19.2@75.819,43.434
  Top Layer-L1 w0.191: v1(14.075,15.4) 14.075,16.575 14.518,17.018 J1.57@15.573,17.018
  Signal-L3 w0.122: v1(14.075,15.4) 14.075,15.343 14.451,14.967 14.451,5.623 19.036,1.039 35.735,1.039 42.048,7.351 45.865,7.351 47.063,8.549 49.27,8.549 50.205,9.484 50.205,19.567 51.117,20.479 51.117,24.609 50.932,24.794 50.932,25.594 51.349,26.011 51.349,27.111 51.082,27.378 51.082,28.393 51.467,28.778 51.467,40.885 51.3,41.052 v1(51.3,42.9) ; v1(72,55.1) 72.468,55.568 74.744,55.568 75.1,55.212 75.1,48.5 75.819,47.781 v1(75.819,41.5)
  Bottom Layer-L6 w0.165: v1(51.3,42.9) 59.604,42.9 63.504,39 65.8,39 67.117,40.317 74.636,40.317 v1(75.819,41.5) ; v1(72,55.1) 72,54.238 SWD.2@72.009,54.229
SYS_RESET: J1.56 J17.18 J19.10 R5.2 SW2.3 SW2.4 SWD.10 | length 149.6
  Top Layer-L1 w0.165: J19.10@70.739,43.434 70.739,44.861 69.9,45.7 69.9,51.161 v1(70.739,52)
  Top Layer-L1 w0.191: v1(13.1,15.4) 13.665,15.965 13.665,17.043 14.91,18.288 J1.56@15.573,18.288 ; v1(39.3,1.572) SW2.3@41.446,1.572 SW2.4@47.246,1.572 48.387,1.572 R5.2@48.387,3.076
  Signal-L3 w0.121: 42.232,4.504 47.86,4.504 55.097,11.741 55.097,18.232 54.632,18.698 54.632,26.107
  Signal-L3 w0.122: v1(13.1,15.4) 13.1,14.9 13.676,14.324 13.676,4.624 v1(15.7,2.6) ; v1(39.3,1.572) 42.232,4.504 ; J17.18@52.07,55.626 52.07,52.68 53.563,51.187 53.563,30.839 53.398,30.674 53.398,28.96 53.382,28.944 53.382,27.356 54.632,26.107
  Bottom Layer-L6 w0.165: J17.18@52.07,55.626 53.331,54.365 58.008,54.365 58.725,55.082 66.493,55.082 69.225,52.35 70.285,52.35 70.635,52 v1(70.739,52) SWD.10@70.739,52.959
  Bottom Layer-L6 w0.191: v1(15.7,2.6) 16.6,2.6 18.3,0.9 38.628,0.9 v1(39.3,1.572)
UART3_RX: J1.70 U2.9 | length 41.5
  Top Layer-L1 w0.191: v1(29.4,12.6) 30.353,11.647 J1.70@30.353,11.088
  Signal-L3 w0.122: v1(17.8,45.6) 17.8,44.2 18.5,43.5 18.5,39.929 21.261,37.168 21.637,37.168 23.7,35.105 23.7,22.5 26.2,20 26.2,14.648 28.248,12.6 v1(29.4,12.6)
  Bottom Layer-L6 w0.165: v1(17.8,45.6) 17.805,45.605 U2.9@18.646,45.605
UART3_TX: J1.71 U2.8 | length 41.3
  Top Layer-L1 w0.191: v1(30.7,12.6) 31.623,11.677 J1.71@31.623,11.088
  Signal-L3 w0.122: v1(18.325,44.5) 18.325,44.027 18.749,43.603 18.749,40.032 21.364,37.417 21.74,37.417 23.949,35.208 23.949,22.603 26.449,20.103 26.449,14.751 28.1,13.1 30.2,13.1 v1(30.7,12.6)
  Bottom Layer-L6 w0.165: v1(18.325,44.5) 18.8,44.5 18.896,44.596 U2.8@18.896,44.955
USB_OTG1_FIL_N: L10.3 R44.1 R48.2 | length 23.1
  Signal-L3 w0.102: v1(62.425,8.95) 62.698,9.223 63.195,9.223 63.371,9.223 63.617,9.223 cw(c63.617,9.117) 63.723,9.117 63.723,8.809 ccw(c63.829,8.809) 63.829,8.704 63.969,8.704 ccw(c63.969,8.809) 64.075,8.809 64.075,9.117 cw(c64.181,9.117) 64.181,9.223 64.211,9.223 65.763,9.223 66.359,9.819 ; 66.37,9.83 67.386,10.846 78.105,10.846 78.918,10.033 78.918,9.53 78.715,9.327 78.416,9.327 v1(78.175,9.569)
  Bottom Layer-L6 w0.127: L10.3@61.675,8.95 v1(62.425,8.95) 62.698,9.223 ; 62.7,9.223 62.925,9.223 63.282,8.866 63.282,8.813 R44.1@63.345,8.75 ; v1(78.175,9.569) 78.416,9.327 78.647,9.327 R48.2@79.12,9.8
USB_OTG1_FIL_P: L10.2 R45.1 R49.2 | length 23.1
  Signal-L3 w0.102: v1(62.425,9.75) 62.698,9.477 65.658,9.477 67.281,11.1 78.21,11.1 79.172,10.138 79.172,9.425 78.82,9.073 78.417,9.073 v1(78.175,8.832)
  Bottom Layer-L6 w0.127: L10.2@61.675,9.75 v1(62.425,9.75) 62.698,9.477 ; 62.7,9.477 62.925,9.477 63.282,9.834 63.282,9.886 R45.1@63.345,9.95 ; v1(78.175,8.832) 78.417,9.073 78.647,9.073 R49.2@79.12,8.6
USB_OTG1_ID: J1.118 R76.2 | length 65.6
  Top Layer-L1 w0.15: J1.118@60.373,47.498 61.698,47.498 v1(61.7,47.5)
  Signal-L3 w0.15: v1(61.7,47.5) 59.5,45.3 59.5,15.6 57.482,13.582 57.482,8.118 58.3,7.3 66.5,7.3 67.225,6.575 v1(79.12,6.575)
  Bottom Layer-L6 w0.15: v1(79.12,6.575) R76.2@79.12,7.45
USB_OTG1_N: J1.114 L10.4 | length 39.2
  Top Layer-L1 w0.127: J1.114@60.373,42.418 60.982,42.418 61.49,41.91 61.959,41.91 v1(62.2,42.151)
  Signal-L3 w0.102: v1(59.05,8.981) 58.809,9.223 58.518,9.223 57.963,9.778 57.963,13.132 59.944,15.113 59.944,40.469 61.385,41.91 61.959,41.91 v1(62.2,42.151)
  Bottom Layer-L6 w0.127: v1(59.05,8.981) 59.292,9.223 59.45,9.223 59.723,8.95 L10.4@60,8.95
USB_OTG1_P: J1.113 L10.1 | length 39.2
  Top Layer-L1 w0.127: J1.113@60.373,41.148 60.948,41.148 61.456,41.656 61.958,41.656 v1(62.2,41.414)
  Signal-L3 w0.102: v1(59.05,9.718) 58.809,9.477 58.623,9.477 58.217,9.883 58.217,10.008 58.217,10.184 58.217,10.43 cw(c58.322,10.43) 58.322,10.535 58.623,10.535 ccw(c58.623,10.641) 58.728,10.641 58.728,10.782 ccw(c58.623,10.782) 58.623,10.887 58.322,10.887 cw(c58.322,10.993) 58.217,10.993 58.217,11.1 58.217,13.027 60.198,15.008 60.198,40.364 61.49,41.656 61.958,41.656 v1(62.2,41.414)
  Bottom Layer-L6 w0.127: v1(59.05,9.718) 59.292,9.477 59.45,9.477 59.723,9.75 L10.1@59.975,9.75
USB_OTG2_FIL_N: L11.3 R46.1 R53.1 | length 56.4
  Top Layer-L1 w0.127: R53.1@71.58,57.3 72.073,57.793 72.073,57.953 v1(71.832,58.195)
  Signal-L3 w0.102: v1(62.425,11.4) 62.152,11.673 61.755,11.673 61.288,12.14 61.288,33.526 61.29,33.528 62.179,34.417 63.221,34.417 63.932,35.128 63.932,50.473 70.177,56.718 71.057,56.718 72.073,57.734 72.073,57.953 v1(71.832,58.195)
  Bottom Layer-L6 w0.127: L11.3@61.675,11.4 v1(62.425,11.4) 62.698,11.673 ; 62.7,11.673 62.925,11.673 63.281,11.317 63.281,11.264 R46.1@63.345,11.2
USB_OTG2_FIL_P: L11.2 R47.1 R52.1 | length 56.4
  Top Layer-L1 w0.127: v1(72.569,58.195) 72.327,57.953 72.327,57.793 R52.1@72.82,57.3
  Signal-L3 w0.102: v1(62.425,12.2) 62.152,11.927 61.86,11.927 61.542,12.245 61.542,12.421 61.542,12.597 61.542,12.843 cw(c61.648,12.843) 61.648,12.948 61.737,12.948 ccw(c61.737,13.054) 61.843,13.054 61.843,13.195 ccw(c61.737,13.195) 61.737,13.3 61.648,13.3 cw(c61.648,13.406) 61.542,13.406 61.542,13.538 61.542,33.421 62.284,34.163 63.326,34.163 63.4,34.237 64.186,35.023 64.186,50.368 70.282,56.464 71.162,56.464 72.327,57.629 72.327,57.953 v1(72.569,58.195)
  Bottom Layer-L6 w0.127: L11.2@61.675,12.2 v1(62.425,12.2) 62.698,11.927 ; 62.7,11.927 62.925,11.927 63.281,12.284 63.281,12.337 R47.1@63.345,12.4
USB_OTG2_N: J1.112 L11.4 | length 34.1
  Top Layer-L1 w0.127: J1.112@60.373,39.878 60.922,39.878 61.43,39.37 61.959,39.37 v1(62.2,39.611)
  Signal-L3 w0.102: v1(59.05,11.432) 59.292,11.673 59.719,11.673 60.909,12.863 60.909,36.039 63.271,38.401 63.271,38.916 62.818,39.37 62.441,39.37 v1(62.2,39.611)
  Bottom Layer-L6 w0.127: v1(59.05,11.432) 59.292,11.673 59.45,11.673 59.723,11.4 L11.4@60,11.4
USB_OTG2_P: J1.111 L11.1 | length 34.1
  Top Layer-L1 w0.127: J1.111@60.373,38.608 60.908,38.608 61.416,39.116 61.958,39.116 v1(62.2,38.874)
  Signal-L3 w0.102: v1(59.05,12.168) 59.292,11.927 59.614,11.927 60.655,12.968 60.655,13.233 60.655,13.304 ccw(c60.55,13.304) 60.55,13.409 60.25,13.409 cw(c60.25,13.515) 60.144,13.515 60.144,13.656 cw(c60.25,13.656) 60.25,13.761 60.55,13.761 ccw(c60.55,13.867) 60.655,13.867 60.655,13.97 60.655,36.144 63.017,38.506 63.017,38.811 62.713,39.116 62.442,39.116 v1(62.2,38.874)
  Bottom Layer-L6 w0.127: v1(59.05,12.168) 59.292,11.927 59.45,11.927 59.723,12.2 L11.1@59.975,12.2
USDHC1_CLK: J1.10 R19.1 | length 46.1
  Top Layer-L1 w0.165: J1.10@45.593,50.888 45.6,50.881 v1(45.6,49.45)
  Bottom Layer-L6 w0.165: R19.1@19.149,29.591 19.149,29.616 19.351,29.818 20.45,29.818 25.05,34.419 25.05,48.729 26.774,50.453 32.018,50.453 32.916,51.35 36.689,51.35 38.589,49.45 v1(45.6,49.45)
USDHC1_CMD: J1.5 J3.3 R14.1 | length 67.6
  Top Layer-L1 w0.165: J1.5@51.943,50.888 51.975,50.856 v1(51.975,49.45)
  Bottom Layer-L6 w0.165: J3.3@4.826,31.328 5.772,31.328 6.3,30.8 6.4,30.8 6.47,30.8 cw(c6.47,30.567) 6.702,30.567 6.702,30.332 ccw(c6.935,30.332) 6.935,30.1 ccw(c6.935,30.332) 7.167,30.332 7.167,30.567 cw(c7.4,30.567) 7.4,30.8 16.308,30.8 16.797,31.29 17.203,31.29 ; 17.203,31.289 17.291,31.289 17.695,30.886 18.111,30.886 18.725,31.5 20.861,31.5 24.7,35.339 24.7,48.792 26.653,50.745 31.897,50.745 32.795,51.642 36.81,51.642 37.844,50.609 50.816,50.609 v1(51.975,49.45) ; R14.1@18.189,30.861 R14.1@18.189,30.886
USDHC1_DATA0: J1.6 J3.7 R18.1 | length 67.5
  Top Layer-L1 w0.165: v1(50.238,49.287) 50.673,49.722 J1.6@50.673,50.888
  Bottom Layer-L6 w0.165: J3.7@4.826,26.928 5.008,27.11 7.11,27.11 7.829,27.829 12.889,27.829 13.997,28.938 16.1,28.938 16.717,28.321 R18.1@18.189,28.321 18.189,28.389 18.75,28.95 20.276,28.95 25.4,34.074 25.4,48.665 26.895,50.16 32.487,50.16 33.384,51.058 36.568,51.058 38.666,48.96 45.803,48.96 46.432,49.59 49.829,49.59 50.131,49.287 v1(50.238,49.287)
USDHC1_DATA1: J1.7 J3.8 R17.1 | length 67.6
  Top Layer-L1 w0.165: v1(48.809,49.1) 49.403,49.694 J1.7@49.403,50.888
  Bottom Layer-L6 w0.165: J3.8@4.826,25.828 6.828,25.828 8,27 13.5,27 14.143,27.643 14.143,27.645 14.309,27.811 17.454,27.811 R17.1@18.189,27.076 ; R17.1@18.189,27.051 R17.1@18.189,27.076 ; v1(48.809,49.1) 48.377,48.668 38.545,48.668 36.447,50.766 33.505,50.766 32.608,49.868 27.016,49.868 25.75,48.602 25.75,32.358 21.003,27.61 20.175,27.61 20.142,27.644 18.747,27.644 18.189,27.086 R17.1@18.189,27.076
USDHC1_DATA2: J1.8 J3.1 R16.1 | length 67.5
  Top Layer-L1 w0.165: v1(48.1,52.3) 48.1,50.921 J1.8@48.133,50.888
  Bottom Layer-L6 w0.165: J3.1@4.826,33.528 6.4,33.528 6.872,34 7.5,34 7.523,34 ccw(c7.523,34.209) 7.733,34.209 7.733,34.341 cw(c7.942,34.341) 7.942,34.55 7.988,34.55 cw(c7.988,34.341) 8.198,34.341 8.198,34 8.198,33.659 ccw(c8.407,33.659) 8.407,33.45 8.453,33.45 ccw(c8.453,33.659) 8.663,33.659 8.663,34 8.663,34.341 cw(c8.872,34.341) 8.872,34.55 8.918,34.55 cw(c8.918,34.341) 9.128,34.341 9.128,34 9.128,33.741 ccw(c9.337,33.741) 9.337,33.532 9.383,33.532 ccw(c9.383,33.741) 9.593,33.741 9.593,34 9.593,34.341 cw(c9.802,34.341) 9.802,34.55 9.848,34.55 cw(c9.848,34.341) 10.058,34.341 10.058,34 10.058,33.659 ccw(c10.267,33.659) 10.267,33.45 10.313,33.45 ccw(c10.313,33.659) 10.523,33.659 10.523,34 10.523,34.341 cw(c10.732,34.341) 10.732,34.55 10.778,34.55 cw(c10.778,34.341) 10.988,34.341 10.988,34 10.988,33.799 ccw(c11.197,33.799) 11.197,33.59 11.243,33.59 ccw(c11.243,33.799) 11.453,33.799 cw(c11.654,33.799) 11.654,34 11.9,34 15.7,34 16.49,33.21 17.998,33.21 R16.1@18.189,33.401 18.189,33.514 18.675,34 20.2,34 24,37.8 24,48.918 26.411,51.329 31.655,51.329 32.553,52.226 37.052,52.226 37.86,51.418 45.326,51.418 46.697,52.79 47.61,52.79 v1(48.1,52.3)
USDHC1_DATA3: J1.9 J3.2 R15.1 | length 67.6
  Top Layer-L1 w0.165: J1.9@46.863,50.888 46.9,50.925 v1(46.9,52.3)
  Bottom Layer-L6 w0.165: J3.2@5.226,32.428 6.2,32.428 6.223,32.428 ccw(c6.223,32.637) 6.433,32.637 6.433,32.993 cw(c6.642,32.993) 6.642,33.202 6.688,33.202 cw(c6.688,32.993) 6.898,32.993 6.898,32.428 6.898,31.863 ccw(c7.107,31.863) 7.107,31.654 7.153,31.654 ccw(c7.153,31.863) 7.363,31.863 7.363,32.428 7.363,32.993 cw(c7.572,32.993) 7.572,33.202 7.618,33.202 cw(c7.618,32.993) 7.828,32.993 7.828,32.428 7.828,31.863 ccw(c8.037,31.863) 8.037,31.654 8.083,31.654 ccw(c8.083,31.863) 8.293,31.863 8.293,32.428 8.293,32.547 cw(c8.502,32.547) 8.502,32.756 8.548,32.756 cw(c8.548,32.547) 8.758,32.547 8.758,32.428 8.758,31.863 ccw(c8.967,31.863) 8.967,31.654 9.013,31.654 ccw(c9.013,31.863) 9.223,31.863 9.223,32.219 cw(c9.432,32.219) 9.432,32.428 9.7,32.428 12.172,32.428 13.5,31.1 16,31.1 16.482,31.582 16.676,31.582 ; 16.676,31.582 17.324,31.582 ; 17.324,31.582 17.412,31.582 17.665,31.582 18.189,32.106 R15.1@18.189,32.131 18.189,32.264 18.725,32.8 20.692,32.8 24.35,36.458 24.35,48.855 26.532,51.037 31.776,51.037 32.674,51.934 36.931,51.934 37.739,51.126 45.726,51.126 v1(46.9,52.3)
USER_BUTTON: J1.86 J17.15 R61.1 | length 102.7
  Top Layer-L1 w0.165: J17.15@44.45,55.626 44.45,54.35 45.2,53.6 v1(45.2,52.9) ; v1(50.673,9.6) J1.86@50.673,11.088
  Signal-L3 w0.121: v1(45.2,52.9) 45.315,53.015 49.146,53.015 51.476,50.686 51.476,43.386 52.059,42.802 52.059,26.715 53.167,25.607 53.167,17.088 50.673,14.594 v1(50.673,9.6) ; v1@50.618,9.545 v1@50.618,9.6
  Signal-L3 w0.122: v1(11,7.635) 12.986,5.65 12.986,3.784 15.98,0.79 35.838,0.79 42.151,7.102 46.002,7.102 47.2,8.3 49.373,8.3 v1@50.618,9.545
  Bottom Layer-L6 w0.165: R61.1@10.189,7.635 v1(11,7.635)
USER_LED: J1.87 J17.14 R59.2 | length 114.2
  Top Layer-L1 w0.165: v1(51.943,9.6) J1.87@51.943,11.088
  Signal-L3 w0.121: v1(1.07,4.053) 3.172,4.053 6.684,0.541 35.941,0.541 41.6,6.2 48.543,6.2 51.879,9.536 51.879,15.063 54.352,17.536 54.352,17.924 53.887,18.389 53.887,25.589 52.637,26.839 52.637,29.253 52.653,29.269 52.653,30.982 52.818,31.147 52.818,50.413 49.279,53.952 43.584,53.952 J17.14@41.91,55.626
  Bottom Layer-L6 w0.165: v1(1.07,4.053) 1.975,4.053 R59.2@2.003,4.025
VCC_LICELL: D1.1 R69.2 | length 36.5
  Signal-L3 w0.4: v1(23.2,40.5) 25.2,38.5 25.2,23.3 v1(24.6,22.7)
  Bottom Layer-L6 w0.4: R69.2@9.68,41.5 11.753,41.5 12.853,42.6 16.1,42.6 18.2,40.5 v1(23.2,40.5) ; D1.1@23.42,20.74 23.42,22.12 24,22.7 v1(24.6,22.7)
VCC_MCA: C4.2 J1.59 J16.2 J17.10 J19.1 R4.1 R5.1 R8.2 SWD.1 SWD.5 | length 214.1
  Top Layer-L1 w0.5: v1(1.125,47.425) 1.15,47.45 v1(1.15,48.2) 3.1,48.2 4.2,49.3 4.2,50.325 5.825,51.95 R8.2@6.1,51.95 ; v1(4,16.7) v1(5,16.7) 11.3,16.7 11.9,16.1 11.9,14.971 12.428,14.443 15.538,14.443 J1.59@15.573,14.478 16.972,14.478 v1(17,14.45) ; R8.2@6.175,52.15 9.696,52.15 11.136,50.71 J16.2@11.14,50.71 ; J16.2@11.14,50.6 J16.2@11.14,50.71 ; J17.10@31.75,55.626 30.165,54.041 22.292,54.041 21.949,53.698 15.528,53.698 15.189,53.359 11.859,53.359 11.14,52.64 J16.2@11.14,50.71 ; v1(47.6,4.036) R5.1@48.387,4.036 ; v1(57.7,4.036) R4.1@58.42,4.036 ; J19.1@75.819,47.498 75.825,47.504 v1(75.825,49.375)
  Signal-L3 w0.8: v1@1.1,48.225 1.1,26 4,23.1 4,17.9 4,17.7 ; v1(6.7,3.5) 6.7,6.8 8.1,8.2 8.1,12 5,15.1 5,15.7 ; v1(4,16.7) 4,17.7 ; v1(4,16.7) 5,15.7 ; v1(4,16.7) v1(5,16.7) ; 4,17.7 v1(5,16.7) ; 5,15.7 v1(5,16.7)
  PWR/Signal-L4 w0.4: J17.10@31.75,55.626 33.05,56.926 58.474,56.926 60.3,55.1 v1(70.75,55.1) 71.457,54.393 75.212,54.393 v1@75.825,55.006 ; v1(75.825,49.375) v1@75.825,55.006 ; v1(75.825,55.1) v1@75.825,55.006
  Bottom Layer-L6 w0.5: v1(6.7,3.5) 17.1,3.5 19.1,1.5 32.8,1.5 33.6,2.3 39.227,2.3 40.963,4.036 v1(47.6,4.036) v1(57.7,4.036) ; SWD.1@70.739,54.229 70.75,54.24 v1(70.75,55.1) ; SWD.5@75.819,54.229 75.825,54.235 v1(75.825,55.1)
  Bottom Layer-L6 w0.8: C4.2@16.12,14.45 v1(17,14.45)
VCC_SCU_1V8: C7.2 R3.2 R10.2 R13.2 U2.7 U2.10 | length 59.7
  Top Layer-L1 w0.5: R10.2@6.449,35.941 7.8,35.941 ; v1(7.15,29.6) 6.887,29.337 R13.2@6.449,29.337 6.449,29.949 7.8,31.3 7.8,35.941 ; v1(10.5,36.8) v1(9.7,36.8) 8.659,36.8 7.8,35.941
  PWR/Signal-L4 w0.5: v1(22.1,41.8) 21.443,41.143 v1(21.443,38) v1(21.443,36.7) 26,32.143 26,14.3 27.043,13.257 30.972,13.257 31.629,12.6 v1(31.7,12.6)
  Bottom Layer-L6 w0.15: U2.10@18.646,46.005 19.145,46.005 19.326,45.824 19.326,45.576 19.296,45.546 U2.7@19.296,44.955
  Bottom Layer-L6 w0.2: C7.2@18.813,43.665 19.296,44.148 U2.7@19.296,44.955
  Bottom Layer-L6 w0.5: v1(9.7,36.8) v1(10.5,36.8) ; C7.2@18.813,43.665 18.813,42.368 19.381,41.8 v1(22.1,41.8) ; v1@21.343,36.8 v1(21.443,36.7) v1(21.443,38) ; v1(31.7,12.6) 31.72,12.58 R3.2@31.72,11.5
VDDCR1: C17.2 C18.2 C19.2 U3.6 | length 4.9
  Bottom Layer-L6 w0.25: C18.2@52.46,27.225 52.46,26.84 53.15,26.15 U3.6@53.45,26.15
  Bottom Layer-L6 w0.4: C18.2@52.46,27.225 52.46,28.631 C19.2@52.435,28.725 52.443,29.043 52.9,29.5 C17.2@52.9,30.3
VIN: C1.2 C2.2 C3.2 C22.2 C23.2 C24.2 C25.2 C33.2 FIL1.3 J11.2 J11.4 J15.1 J18.1 L7.1 L8.2 L9.2 L16.1 R2.1 R43.1 R51.1 U1.1 U1.3 U9.1 | length 53.3
  Top Layer-L1 w0.61: R2.1@6.1,48.15 7.55,48.15 J15.1@8.6,47.1 ; C33.2@11.4,9.535 11.96,9.535 12.075,9.65 v1(12.5,9.65) ; v1(63.6,13.2) v1(64.26,13.2) C23.2@64.26,11.4 C22.2@64.26,10.2 65.95,10.2 L8.2@65.95,9.8 ; L9.2@65.95,7.7 64.65,9 C24.2@64.26,9 C25.2@64.26,7.8 64.26,7.14 65.7,5.7 v1(66.1,5.7) v1(66.8,5.7) ; v1(75.975,58.075) 75.975,57.305 R51.1@75.98,57.3
  Top Layer-L1 w0.762: v1(8.3,29.2) 8.2,29.3 v1(8.2,30.225) 11.559,30.225 C1.2@11.565,30.231
  Bottom Layer-L6 w0.61: v1(8.5,17.6) v1(9.2,17.6) 9.6,17.2 14.6,17.2 15.8,18.4 C3.2@18.1,18.4 20.525,18.4 20.725,18.6 ; v1(12.5,8.9) 13.15,8.9 L7.1@13.55,9.3 ; v1(12.5,9.65) L7.1@13.15,9.65 ; L7.1@13.475,9.7 14.425,10.65 16.475,10.65 16.8,10.325 R43.1@16.8,9.875 ; U1.3@22.08,17.35 21.424,17.35 20.725,18.049 20.725,18.6 ; U1.1@22.08,19.25 21.375,19.25 20.725,18.6 ; J18.1@45.72,12.065 45.72,9.68 46.6,8.8 v1(46.6,6.8) ; v1(83.614,45.5) 83.614,46.1 L16.1@84.056,46.542 84.514,46.084 v1(84.514,45.5)
  other v1: 9.1,29.2
XBEE_ON/SLP_N: J1.36 J13.8 J17.13 | length 79
  Top Layer-L1 w0.165: J1.36@15.573,43.688 16.888,43.688 v1(16.9,43.7)
  Signal-L3 w0.121: 32.961,54.861 32.961,55.903 33.82,56.761 38.235,56.761 J17.13@39.37,55.626
  Signal-L3 w0.122: v1(16.9,43.7) 16.284,44.316 16.284,46.335 17.196,47.248 19.991,47.248 20.901,46.337 22.333,46.337 29.844,53.848 31.948,53.848 32.961,54.861 ; v1(69.4,51.4) 69.4,41.3 71.217,39.483 J13.8@71.217,38.354
  Bottom Layer-L6 w0.165: J17.13@39.37,55.626 40.714,54.282 50.126,54.282 50.919,53.489 67.26,53.489 69.349,51.4 v1(69.4,51.4)
XBEE_RESET: J1.35 J12.5 J17.11 | length 82.3
  Top Layer-L1 w0.165: J1.35@15.573,44.958 v1(16.9,44.958)
  Signal-L3 w0.121: v1(16.9,44.958) 16.532,45.325 16.532,46.233 17.299,46.999 19.888,46.999 20.798,46.089 22.436,46.089 29.947,53.6 32.264,53.6 J17.11@34.29,55.626 36.616,53.3 44.139,53.3 45.006,52.433 46.371,52.433 46.706,52.767 48.733,52.767 v1(49.1,52.4)
  Signal-L3 w0.122: J12.5@77.217,60.325 77.217,58.708 78.6,57.325 v1(78.6,50.7)
  Bottom Layer-L6 w0.165: v1(49.1,52.4) 49.18,52.32 62.706,52.32 64.7,50.326 78.226,50.326 v1(78.6,50.7)
XBEE_SLEEP_RQ: J1.26 J12.9 J17.12 R54.2 | length 56.8
  Top Layer-L1 w0.165: J1.26@25.273,50.888 25.273,52.373 v1(25.7,52.8) ; v1(68.1,51.4) 68.1,54.6 69.079,55.579 R54.2@69.079,57.331 69.079,60.187 J12.9@69.217,60.325
  Bottom Layer-L6 w0.165: v1(25.7,52.8) 26.7,53.8 35.004,53.8 J17.12@36.83,55.626 36.966,55.626 38.603,53.99 50.005,53.99 50.798,53.197 66.303,53.197 v1(68.1,51.4)
XBEE_UART_CTS: J1.81 J13.9 | length 59.8
  Top Layer-L1 w0.165: v1(44.323,9.6) J1.81@44.323,11.088
  Signal-L3 w0.122: v1(44.323,9.6) 46.625,11.902 48.402,11.902 49.956,13.456 49.956,19.67 50.868,20.582 50.868,24.472 50.683,24.656 50.683,25.697 51.1,26.114 51.1,27.008 50.783,27.325 50.783,28.446 51.218,28.881 51.218,40.782 v1(50.2,41.8)
  Bottom Layer-L6 w0.165: v1(50.2,41.8) 57.6,41.8 61.015,38.385 65.785,38.385 66.9,39.5 68.071,39.5 J13.9@69.217,38.354
XBEE_UART_RTS: J1.80 J13.5 R57.2 | length 70.6
  Top Layer-L1 w0.165: v1(43.053,9.6) J1.80@43.053,11.088 ; J13.5@77.217,38.354 77.234,38.354 R57.2@80.6,41.72
  Signal-L3 w0.122: v1(43.053,9.6) 45.604,12.151 48.299,12.151 49.232,13.084 49.232,39.632 v1(50.2,40.6)
  Bottom Layer-L6 w0.165: v1(50.2,40.6) 57.518,40.6 60.781,37.336 76.199,37.336 J13.5@77.217,38.354
XBEE_UART_RX: J1.14 R62.1 R67.2 | length 71
  Top Layer-L1 w0.165: v1(82.2,53.2) R62.1@82.2,56.52
  Top Layer-L1 w0.191: v1(40.5,52.2) 40.513,52.187 J1.14@40.513,50.888
  Bottom Layer-L6 w0.165: R67.2@22.175,47.535 21.71,48 21.71,48.503 22.168,48.96 23.216,48.96 26.523,52.267 31.767,52.267 32.59,53.09 39.61,53.09 v1(40.5,52.2) 41.69,53.39 50.192,53.39 50.677,52.904 62.948,52.904 64.942,50.91 76.96,50.91 79.25,53.2 v1(82.2,53.2)
XBEE_UART_TX: J1.13 R63.1 R66.2 | length 68.7
  Top Layer-L1 w0.165: v1(80.8,52.3) R63.1@80.8,56.52
  Top Layer-L1 w0.191: J1.13@41.783,50.888 v1(41.783,52.2)
  Bottom Layer-L6 w0.165: R66.2@23.375,47.535 23.375,48.706 26.29,51.621 31.534,51.621 32.432,52.518 37.173,52.518 37.981,51.71 41.293,51.71 v1(41.783,52.2) 42.273,51.71 45.205,51.71 46.576,53.082 50.087,53.082 50.556,52.612 62.827,52.612 64.821,50.618 77.143,50.618 78.825,52.3 v1(80.8,52.3)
